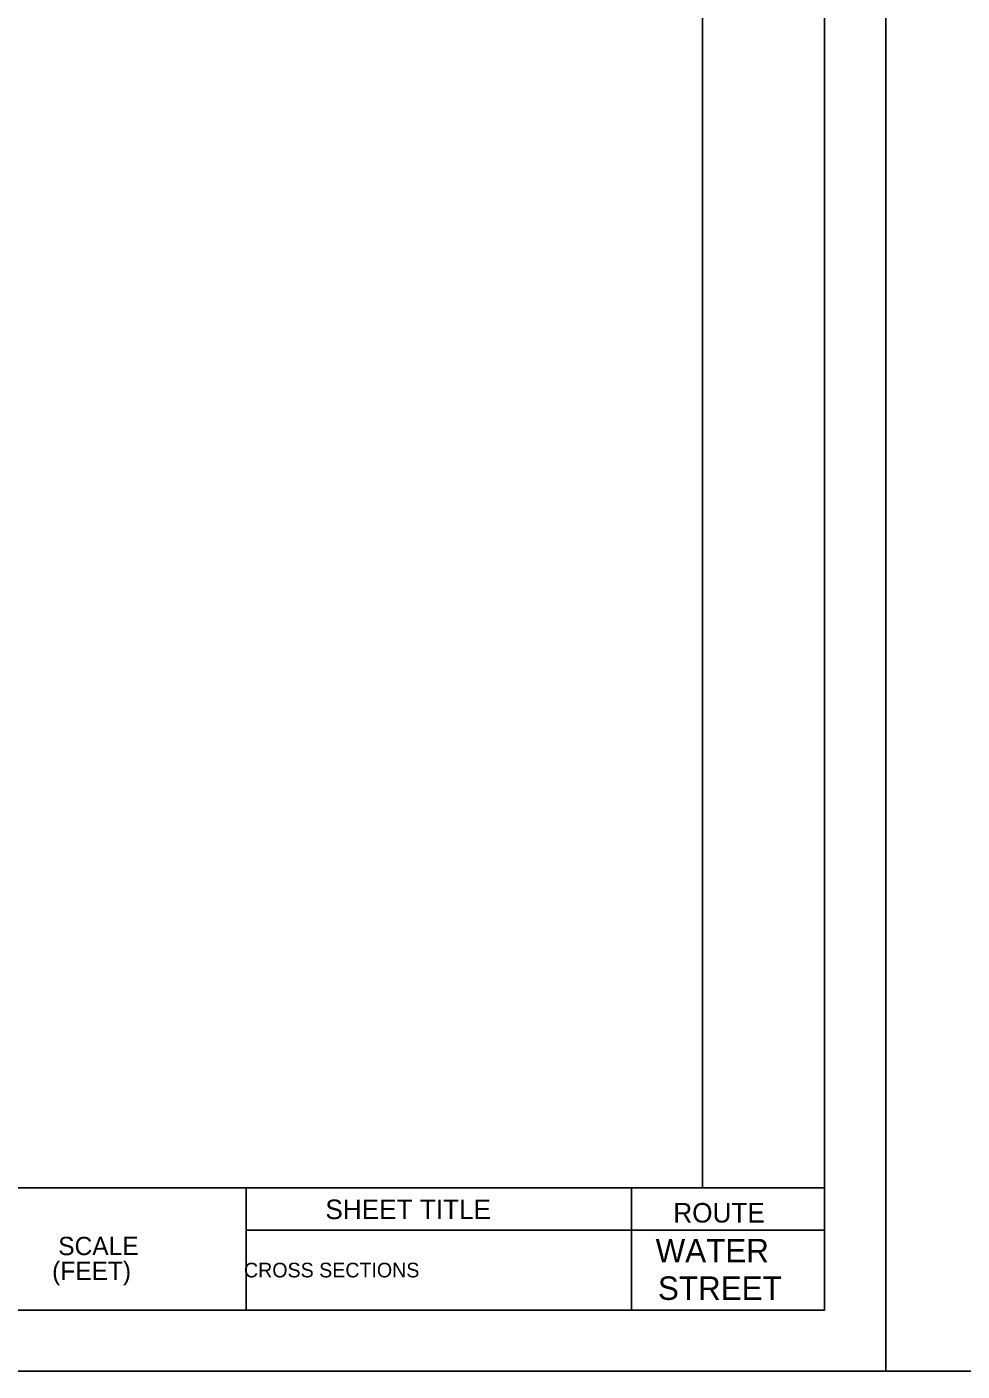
# Model space of a CAD drawing. Extents: x 1797478 to 1808916, y 246529 to 250952.
# Drawn here: x 1803405.7 to 1803482.3, y 250064.4 to 250174.4 of the extents above; entities that cross this region are included whole.
import ezdxf

# ---------------------------------------------------------------- set-up
doc = ezdxf.new("R2010")
doc.units = 0
for name, color, linetype in [('ANNO-SHT', 7, 'Continuous'), ('ANNO-SYMB', 7, 'Continuous'), ('ANNO-TXT', 7, 'Continuous'), ('Level 6', 7, 'Continuous'), ('Level 62', 7, 'Continuous'), ('SHT-BDR', 7, 'Continuous'), ('SHT-BNDRY', 7, 'Continuous')]:
    doc.layers.add(name, color=color, linetype=linetype)

msp = doc.modelspace()

# ---------------------------------------------------------------- linework, layer by layer
at = {"layer": 'ANNO-TXT'}
for p, q in [((1803423.66, 250075.96), (1803455.19, 250075.96)), ((1803455.19, 250075.96), (1803471, 250075.96))]:
    msp.add_line(p, q, dxfattribs=at)
at = {"layer": 'Level 6'}
msp.add_line((1803471, 250079.43), (1803423.66, 250079.43), dxfattribs=at)
at = {"layer": 'Level 62'}
for points in [[(1803136, 250064.42), (1803476, 250064.42), (1803476, 250284.42), (1803136, 250284.42)], [(1803476, 250064.42), (1803816, 250064.42), (1803816, 250284.42), (1803476, 250284.42)]]:
    msp.add_lwpolyline(points, close=True, dxfattribs=at)
at = {"layer": 'SHT-BDR'}
msp.add_lwpolyline([(1803161, 250079.43), (1803461, 250079.43), (1803461, 250269.43), (1803161, 250269.43)], close=True, dxfattribs=at)
at = {"layer": 'SHT-BNDRY'}
for p, q in [((1803423.66, 250069.42), (1803423.66, 250079.43)), ((1803455.19, 250069.42), (1803455.19, 250079.43))]:
    msp.add_line(p, q, dxfattribs=at)
msp.add_lwpolyline([(1803148.5, 250069.42), (1803471, 250069.42), (1803471, 250279.42), (1803148.5, 250279.42)], close=True, dxfattribs=at)

# ---------------------------------------------------------------- texts
at = {"layer": 'ANNO-SHT'}
for s, height, p in [(' WATER ', 1.92, (1803456.46, 250073.32)), ('          CROSS SECTIONS          ', 1.2, (1803419.03, 250072.09)), (' STREET ', 1.92, (1803456.65, 250070.25))]:
    msp.add_text(s, height=height, rotation=360, dxfattribs=at).set_placement(p)
at = {"layer": 'ANNO-SYMB'}
for s, p in [('SCALE', (1803408.29, 250073.91)), ('(FEET)', (1803407.79, 250071.88))]:
    msp.add_text(s, height=1.499, rotation=0.0572, dxfattribs=at).set_placement(p)
at = {"layer": 'ANNO-TXT'}
for s, p in [('SHEET TITLE', (1803430.15, 250076.86)), ('ROUTE', (1803458.62, 250076.58))]:
    msp.add_text(s, height=1.6, dxfattribs=at).set_placement(p)

doc.saveas('drawing.dxf')
